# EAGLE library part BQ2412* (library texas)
SINGLE-CHIP SWITCHMODE, LI-ION AND LI-POLYMER CHARGE-MANAGEMENT WITH ENHANCED EMI PERFORMANCE(bqSWITCHER TM) Source: http://focus.ti.com/lit/ds/symlink/bq24120.pdf
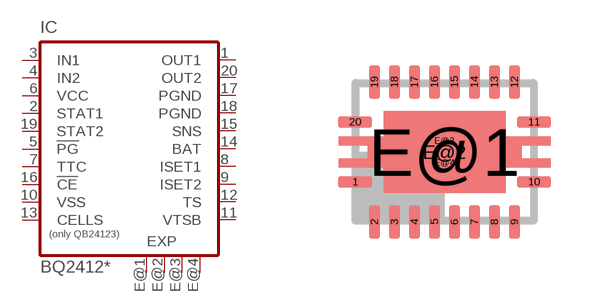
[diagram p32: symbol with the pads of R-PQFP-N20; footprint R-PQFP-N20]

Designator prefix IC

## BQ24120 (MPN: BQ24120RHLTG4; OC_FARNELL: 1230453; OC_NEWARK: 12M9386), BQ24123 (MPN: BQ24123RHLT; OC_FARNELL: 1407131; OC_NEWARK: 84K0851)  [R-PQFP-N20]
1  OUT1  pas
2  STAT1  out
3  IN1  in
4  IN2  in
5  !PG  out
6  VCC  in
7  TTC  in
8  ISET1
9  ISET2
10  VSS  in
11  VTSB  out
12  TS  in
13  CELLS  in
14  BAT  in
15  SNS  in
16  !CE  in
17  PGND  pas
18  PGND  pas
19  STAT2  out
20  OUT2  pas
E@1  EXP  pas
E@2  EXP  pas
E@3  EXP  pas
E@4  EXP  pas

## Footprint R-PQFP-N20 (pad centres in mm)
PQFP20 RHL PACKAGE 4.5mm x 3.5mm QFN Source: http://focus.ti.com/lit/ds/symlink/tps75003.pdf
smd 0.85 x 0.28: 1 -2.235,-0.75; 10 2.235,-0.75; 11 2.235,0.75; 20 -2.235,0.75
smd 0.28 x 0.85: 2 -1.75,-1.75; 3 -1.25,-1.75; 4 -0.75,-1.75; 5 -0.25,-1.75; 6 0.25,-1.75; 7 0.75,-1.75; 8 1.25,-1.75; 9 1.75,-1.75; 12 1.75,1.75; 13 1.25,1.75; 14 0.75,1.75; 15 0.25,1.75; 16 -0.25,1.75; 17 -0.75,1.75; 18 -1.25,1.75; 19 -1.75,1.75
smd 3.05 x 2.05: E@1 0,0
smd 3.85 x 0.5: E@2 0,0
smd 5.3 x 0.23: E@3 0,0.275; E@4 0,-0.275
